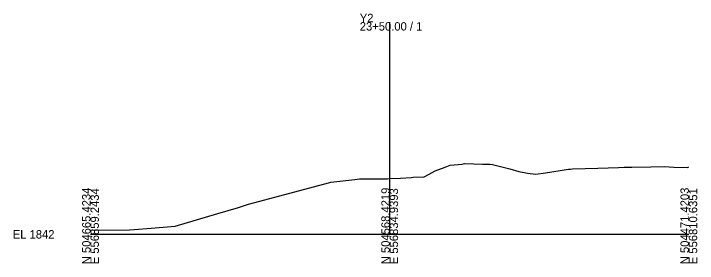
# Model space of a CAD drawing. Extents: x -26 to 203, y -10 to 3574.
# Drawn here: x -25.7 to 202.8, y 3490.3 to 3573.8 of the extents above; entities that cross this region are included whole.
import ezdxf

# ---------------------------------------------------------------- set-up
doc = ezdxf.new("R2010")
doc.units = 0
doc.layers.add('Exist Cross Section Cell', color=7, linetype='Continuous')
doc.layers.add('Exist XS Ground Line', color=7, linetype='Continuous')

msp = doc.modelspace()

# ---------------------------------------------------------------- linework, layer by layer
at = {"layer": 'Exist Cross Section Cell'}
for p, q in [((100, 3500), (100, 3570.91)), ((0, 3500), (100, 3500)), ((100, 3500), (200, 3500))]:
    msp.add_line(p, q, dxfattribs=at)
at = {"layer": 'Exist XS Ground Line'}
for p, q in [((115.21, 3521.22), (118.51, 3522.47)), ((118.51, 3522.47), (120.23, 3523.11)), ((120.23, 3523.11), (124.19, 3523.49)), ((124.19, 3523.49), (124.96, 3523.64)), ((124.96, 3523.64), (131.08, 3523.43)), ((131.08, 3523.43), (132.72, 3523.47)), ((132.72, 3523.47), (133.44, 3523.4)), ((133.44, 3523.4), (134.38, 3523.29)), ((134.38, 3523.29), (140.2, 3521.89)), ((140.2, 3521.89), (143.2, 3521)), ((152.08, 3520.53), (159.8, 3521.8)), ((159.8, 3521.8), (160.39, 3521.82)), ((160.39, 3521.82), (161.07, 3521.84)), ((161.07, 3521.84), (169.55, 3522.12)), ((169.55, 3522.12), (176.45, 3522.39)), ((176.45, 3522.39), (178.39, 3522.41)), ((178.39, 3522.41), (180.98, 3522.46)), ((180.98, 3522.46), (187.31, 3522.55)), ((187.31, 3522.55), (191.85, 3522.63)), ((191.85, 3522.63), (194.97, 3522.46)), ((194.97, 3522.46), (199.52, 3522.29)), ((199.52, 3522.29), (200, 3522.51)), ((111.55, 3519.27), (113.17, 3520.09)), ((113.17, 3520.09), (115.21, 3521.22)), ((143.2, 3521), (146.07, 3520.44)), ((146.07, 3520.44), (148.87, 3520.09)), ((148.87, 3520.09), (152.08, 3520.53)), ((52.79, 3510.06), (80, 3517.31)), ((80, 3517.31), (80.38, 3517.39)), ((80.38, 3517.39), (88.4, 3518.33)), ((88.4, 3518.33), (89.89, 3518.58)), ((89.89, 3518.58), (91.27, 3518.59)), ((91.27, 3518.59), (99.29, 3518.59)), ((99.29, 3518.59), (100, 3518.63)), ((100, 3518.63), (103.57, 3518.79)), ((103.57, 3518.79), (107.34, 3518.99)), ((107.34, 3518.99), (107.9, 3519.05)), ((107.9, 3519.05), (111.55, 3519.27)), ((42.55, 3506.97), (49.44, 3508.99)), ((49.44, 3508.99), (52.79, 3510.06)), ((28.24, 3502.7), (42.55, 3506.97)), ((0, 3501.36), (12.98, 3501.49)), ((12.98, 3501.49), (14.61, 3501.59)), ((14.61, 3501.59), (20.29, 3502.06)), ((20.29, 3502.06), (28.24, 3502.7))]:
    msp.add_line(p, q, dxfattribs=at)

# ---------------------------------------------------------------- texts
at = {"layer": 'Exist Cross Section Cell'}
for s, p in [('Y2', (90, 3570.91)), ('23+50.00 / 1', (90, 3568.11)), ('EL 1842', (-26, 3498.6))]:
    msp.add_text(s, height=2.8, dxfattribs=at).set_placement(p)
for s, p in [('N 504665.4234', (0, 3490)), ('E 556859.2434', (2.8, 3490)), ('N 504568.4219', (100, 3490)), ('E 556834.9393', (102.8, 3490)), ('N 504471.4203', (200, 3490)), ('E 556810.6351', (202.8, 3490))]:
    msp.add_text(s, height=2.8, rotation=90, dxfattribs=at).set_placement(p)

doc.saveas('drawing.dxf')
